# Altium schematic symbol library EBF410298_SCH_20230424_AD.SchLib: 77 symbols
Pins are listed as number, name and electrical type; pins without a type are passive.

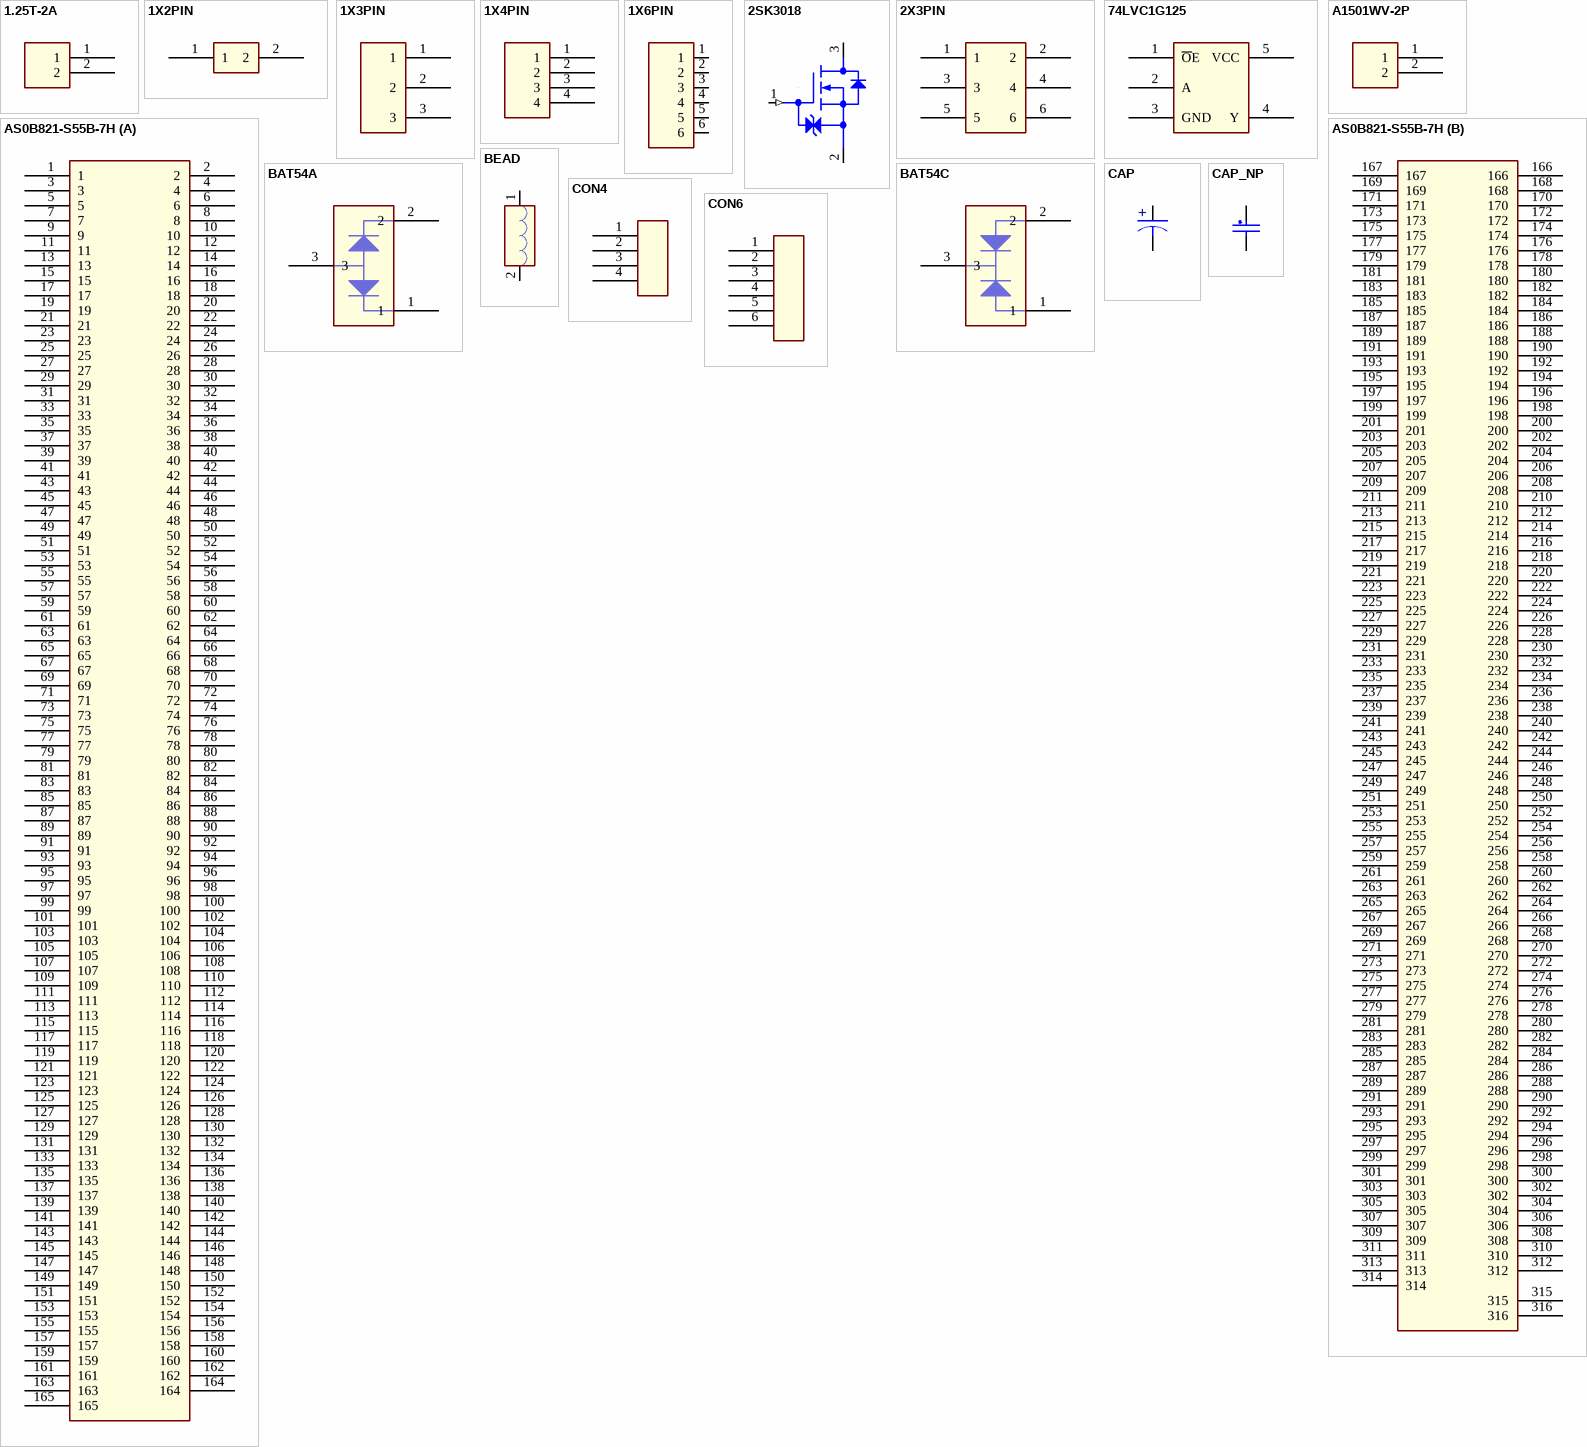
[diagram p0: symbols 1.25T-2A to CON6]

## 1.25T-2A
designator J?
footprint gh1p25_th_2p
pins: 1, 2

## 1X2PIN
designator J?
pins: 1, 2

## 1X3PIN
designator J?
pins: 1, 2, 3

## 1X4PIN
designator J?
pins: 1, 2, 3, 4

## 1X6PIN
designator J?
pins: 1, 2, 3, 4, 5, 6

## 2SK3018
designator Q?
CLASS: IC
pins: 1 GATE (in), 2 SOURCE, 3 DRAIN

## 2X3PIN
designator J?
pins: 1, 2, 3, 4, 5, 6

## 74LVC1G125
designator U?
footprint SOT-353
pins: 1 ~{O}E, 2 A, 3 GND, 4 Y, 5 VCC

## A1501WV-2P
designator J?
pins: 1, 2

## AS0B821-S55B-7H
designator J?
footprint AS0B821-S55B-7H
part A pins: 1, 2, 3, 4, 5, 6, 7, 8, 9, 10, 11, 12, 13, 14, 15, 16, 17, 18, 19, 20, 21, 22, 23, 24, 25, 26, 27, 28, 29, 30, 31, 32, 33, 34, 35, 36, 37, 38, 39, 40, 41, 42, 43, 44, 45, 46, 47, 48, 49, 50, 51, 52, 53, 54, 55, 56, 57, 58, 59, 60, 61, 62, 63, 64, 65, 66, 67, 68, 69, 70, 71, 72, 73, 74, 75, 76, 77, 78, 79, 80, 81, 82, 83, 84, 85, 86, 87, 88, 89, 90, 91, 92, 93, 94, 95, 96, 97, 98, 99, 100, 101, 102, 103, 104, 105, 106, 107, 108, 109, 110, 111, 112, 113, 114, 115, 116, 117, 118, 119, 120, 121, 122, 123, 124, 125, 126, 127, 128, 129, 130, 131, 132, 133, 134, 135, 136, 137, 138, 139, 140, 141, 142, 143, 144, 145, 146, 147, 148, 149, 150, 151, 152, 153, 154, 155, 156, 157, 158, 159, 160, 161, 162, 163, 164, 165
part B pins: 166, 167, 168, 169, 170, 171, 172, 173, 174, 175, 176, 177, 178, 179, 180, 181, 182, 183, 184, 185, 186, 187, 188, 189, 190, 191, 192, 193, 194, 195, 196, 197, 198, 199, 200, 201, 202, 203, 204, 205, 206, 207, 208, 209, 210, 211, 212, 213, 214, 215, 216, 217, 218, 219, 220, 221, 222, 223, 224, 225, 226, 227, 228, 229, 230, 231, 232, 233, 234, 235, 236, 237, 238, 239, 240, 241, 242, 243, 244, 245, 246, 247, 248, 249, 250, 251, 252, 253, 254, 255, 256, 257, 258, 259, 260, 261, 262, 263, 264, 265, 266, 267, 268, 269, 270, 271, 272, 273, 274, 275, 276, 277, 278, 279, 280, 281, 282, 283, 284, 285, 286, 287, 288, 289, 290, 291, 292, 293, 294, 295, 296, 297, 298, 299, 300, 301, 302, 303, 304, 305, 306, 307, 308, 309, 310, 311, 312, 313, 314, 315, 316

## BAT54A
designator D?
footprint SOT23
pins: 1, 2, 3

## BAT54C
designator D?
footprint SOT23
pins: 1, 2, 3

## BEAD
designator L?
CLASS: DISCRETE
pins: 1, 2

## CAP
designator C?
footprint T2012
pins: 1, 2

## CAP_NP
designator C?
CLASS: DISCRETE
pins: 1, 2

## CON4
designator J?
pins: 1, 2, 3, 4

## CON6
designator J?
pins: 1, 2, 3, 4, 5, 6

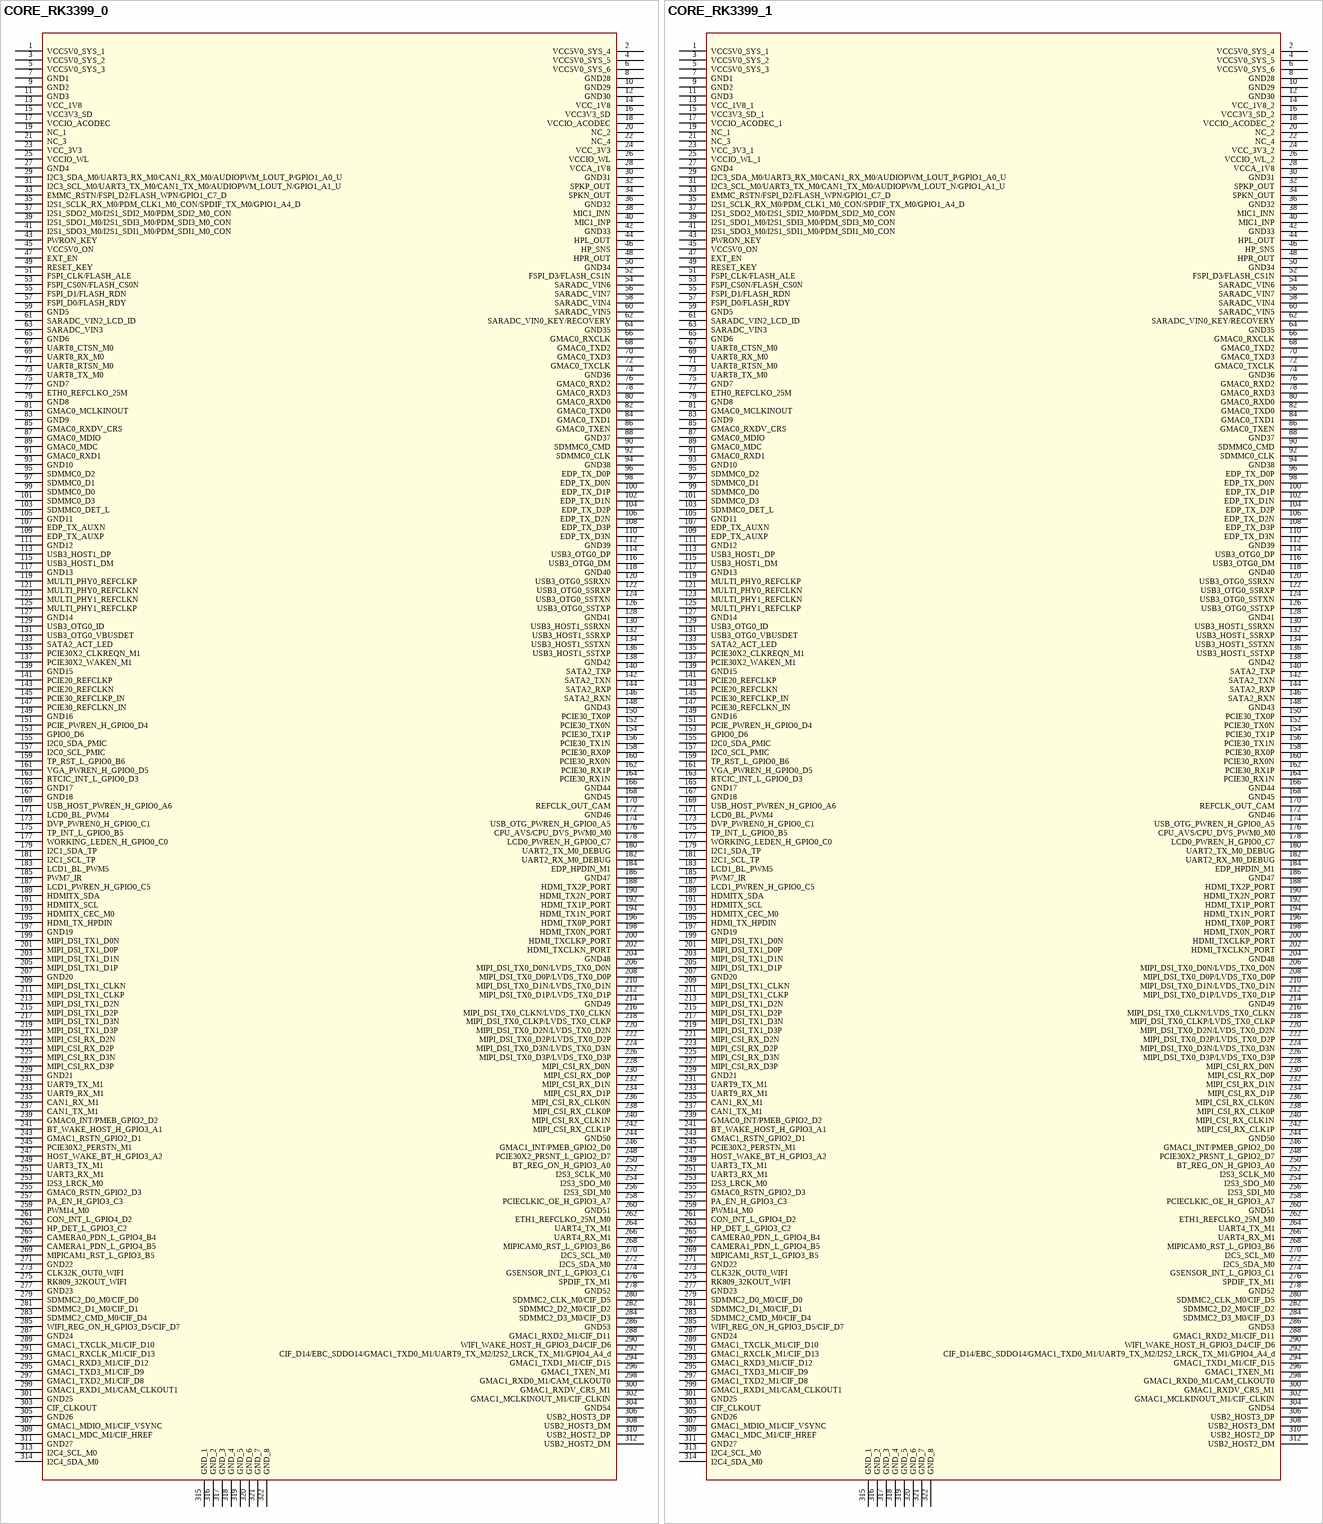
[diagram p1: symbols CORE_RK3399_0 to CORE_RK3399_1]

## CORE_RK3399_0
designator U?
pins: 1 VCC5V0_SYS_1, 2 VCC5V0_SYS_4, 3 VCC5V0_SYS_2, 4 VCC5V0_SYS_5, 5 VCC5V0_SYS_3, 6 VCC5V0_SYS_6, 7 GND1, 8 GND28, 9 GND2, 10 GND29, 11 GND3, 12 GND30, 13 VCC_1V8, 14 VCC_1V8, 15 VCC3V3_SD, 16 VCC3V3_SD, 17 VCCIO_ACODEC, 18 VCCIO_ACODEC, 19 NC_1, 20 NC_2, 21 NC_3, 22 NC_4, 23 VCC_3V3, 24 VCC_3V3, 25 VCCIO_WL, 26 VCCIO_WL, 27 GND4, 28 VCCA_1V8, 29 I2C3_SDA_M0/UART3_RX_M0/CAN1_RX_M0/AUDIOPWM_LOUT_P/GPIO1_A0_U, 30 GND31, 31 I2C3_SCL_M0/UART3_TX_M0/CAN1_TX_M0/AUDIOPWM_LOUT_N/GPIO1_A1_U, 32 SPKP_OUT, 33 EMMC_RSTN/FSPI_D2/FLASH_WPN/GPIO1_C7_D, 34 SPKN_OUT, 35 I2S1_SCLK_RX_M0/PDM_CLK1_M0_CON/SPDIF_TX_M0/GPIO1_A4_D, 36 GND32, 37 I2S1_SDO2_M0/I2S1_SDI2_M0/PDM_SDI2_M0_CON, 38 MIC1_INN, 39 I2S1_SDO1_M0/I2S1_SDI3_M0/PDM_SDI3_M0_CON, 40 MIC1_INP, 41 I2S1_SDO3_M0/I2S1_SDI1_M0/PDM_SDI1_M0_CON, 42 GND33, 43 PWRON_KEY, 44 HPL_OUT, 45 VCC5V0_ON, 46 HP_SNS, 47 EXT_EN, 48 HPR_OUT, 49 RESET_KEY, 50 GND34, 51 FSPI_CLK/FLASH_ALE, 52 FSPI_D3/FLASH_CS1N, 53 FSPI_CS0N/FLASH_CS0N, 54 SARADC_VIN6, 55 FSPI_D1/FLASH_RDN, 56 SARADC_VIN7, 57 FSPI_D0/FLASH_RDY, 58 SARADC_VIN4, 59 GND5, 60 SARADC_VIN5, 61 SARADC_VIN2_LCD_ID, 62 SARADC_VIN0_KEY/RECOVERY, 63 SARADC_VIN3, 64 GND35, 65 GND6, 66 GMAC0_RXCLK, 67 UART8_CTSN_M0, 68 GMAC0_TXD2, 69 UART8_RX_M0, 70 GMAC0_TXD3, 71 UART8_RTSN_M0, 72 GMAC0_TXCLK, 73 UART8_TX_M0, 74 GND36, 75 GND7, 76 GMAC0_RXD2, 77 ETH0_REFCLKO_25M, 78 GMAC0_RXD3, 79 GND8, 80 GMAC0_RXD0, 81 GMAC0_MCLKINOUT, 82 GMAC0_TXD0, 83 GND9, 84 GMAC0_TXD1, 85 GMAC0_RXDV_CRS, 86 GMAC0_TXEN, 87 GMAC0_MDIO, 88 GND37, 89 GMAC0_MDC, 90 SDMMC0_CMD, 91 GMAC0_RXD1, 92 SDMMC0_CLK, 93 GND10, 94 GND38, 95 SDMMC0_D2, 96 EDP_TX_D0P, 97 SDMMC0_D1, 98 EDP_TX_D0N, 99 SDMMC0_D0, 100 EDP_TX_D1P, 101 SDMMC0_D3, 102 EDP_TX_D1N, 103 SDMMC0_DET_L, 104 EDP_TX_D2P, 105 GND11, 106 EDP_TX_D2N, 107 EDP_TX_AUXN, 108 EDP_TX_D3P, 109 EDP_TX_AUXP, 110 EDP_TX_D3N, 111 GND12, 112 GND39, 113 USB3_HOST1_DP, 114 USB3_OTG0_DP, 115 USB3_HOST1_DM, 116 USB3_OTG0_DM, 117 GND13, 118 GND40, 119 MULTI_PHY0_REFCLKP, 120 USB3_OTG0_SSRXN, 121 MULTI_PHY0_REFCLKN, 122 USB3_OTG0_SSRXP, 123 MULTI_PHY1_REFCLKN, 124 USB3_OTG0_SSTXN, 125 MULTI_PHY1_REFCLKP, 126 USB3_OTG0_SSTXP, 127 GND14, 128 GND41, 129 USB3_OTG0_ID, 130 USB3_HOST1_SSRXN, 131 USB3_OTG0_VBUSDET, 132 USB3_HOST1_SSRXP, 133 SATA2_ACT_LED, 134 USB3_HOST1_SSTXN, 135 PCIE30X2_CLKREQN_M1, 136 USB3_HOST1_SSTXP, 137 PCIE30X2_WAKEN_M1, 138 GND42, 139 GND15, 140 SATA2_TXP, 141 PCIE20_REFCLKP, 142 SATA2_TXN, 143 PCIE20_REFCLKN, 144 SATA2_RXP, 145 PCIE30_REFCLKP_IN, 146 SATA2_RXN, 147 PCIE30_REFCLKN_IN, 148 GND43, 149 GND16, 150 PCIE30_TX0P, 151 PCIE_PWREN_H_GPIO0_D4, 152 PCIE30_TX0N, 153 GPIO0_D6, 154 PCIE30_TX1P, 155 I2C0_SDA_PMIC, 156 PCIE30_TX1N, 157 I2C0_SCL_PMIC, 158 PCIE30_RX0P, 159 TP_RST_L_GPIO0_B6, 160 PCIE30_RX0N, 161 VGA_PWREN_H_GPIO0_D5, 162 PCIE30_RX1P, 163 RTCIC_INT_L_GPIO0_D3, 164 PCIE30_RX1N, 165 GND17, 166 GND44, 167 GND18, 168 GND45, 169 USB_HOST_PWREN_H_GPIO0_A6, 170 REFCLK_OUT_CAM, 171 LCD0_BL_PWM4, 172 GND46, 173 DVP_PWREN0_H_GPIO0_C1, 174 USB_OTG_PWREN_H_GPIO0_A5, 175 TP_INT_L_GPIO0_B5, 176 CPU_AVS/CPU_DVS_PWM0_M0, 177 WORKING_LEDEN_H_GPIO0_C0, 178 LCD0_PWREN_H_GPIO0_C7, 179 I2C1_SDA_TP, 180 UART2_TX_M0_DEBUG, 181 I2C1_SCL_TP, 182 UART2_RX_M0_DEBUG, 183 LCD1_BL_PWM5, 184 EDP_HPDIN_M1, 185 PWM7_IR, 186 GND47, 187 LCD1_PWREN_H_GPIO0_C5, 188 HDMI_TX2P_PORT, 189 HDMITX_SDA, 190 HDMI_TX2N_PORT, 191 HDMITX_SCL, 192 HDMI_TX1P_PORT, 193 HDMITX_CEC_M0, 194 HDMI_TX1N_PORT, 195 HDMI_TX_HPDIN, 196 HDMI_TX0P_PORT, 197 GND19, 198 HDMI_TX0N_PORT, 199 MIPI_DSI_TX1_D0N, 200 HDMI_TXCLKP_PORT, 201 MIPI_DSI_TX1_D0P, 202 HDMI_TXCLKN_PORT, 203 MIPI_DSI_TX1_D1N, 204 GND48, 205 MIPI_DSI_TX1_D1P, 206 MIPI_DSI_TX0_D0N/LVDS_TX0_D0N, 207 GND20, 208 MIPI_DSI_TX0_D0P/LVDS_TX0_D0P, 209 MIPI_DSI_TX1_CLKN, 210 MIPI_DSI_TX0_D1N/LVDS_TX0_D1N, 211 MIPI_DSI_TX1_CLKP, 212 MIPI_DSI_TX0_D1P/LVDS_TX0_D1P, 213 MIPI_DSI_TX1_D2N, 214 GND49, 215 MIPI_DSI_TX1_D2P, 216 MIPI_DSI_TX0_CLKN/LVDS_TX0_CLKN, 217 MIPI_DSI_TX1_D3N, 218 MIPI_DSI_TX0_CLKP/LVDS_TX0_CLKP, 219 MIPI_DSI_TX1_D3P, 220 MIPI_DSI_TX0_D2N/LVDS_TX0_D2N, 221 MIPI_CSI_RX_D2N, 222 MIPI_DSI_TX0_D2P/LVDS_TX0_D2P, 223 MIPI_CSI_RX_D2P, 224 MIPI_DSI_TX0_D3N/LVDS_TX0_D3N, 225 MIPI_CSI_RX_D3N, 226 MIPI_DSI_TX0_D3P/LVDS_TX0_D3P, 227 MIPI_CSI_RX_D3P, 228 MIPI_CSI_RX_D0N, 229 GND21, 230 MIPI_CSI_RX_D0P, 231 UART9_TX_M1, 232 MIPI_CSI_RX_D1N, 233 UART9_RX_M1, 234 MIPI_CSI_RX_D1P, 235 CAN1_RX_M1, 236 MIPI_CSI_RX_CLK0N, 237 CAN1_TX_M1, 238 MIPI_CSI_RX_CLK0P, 239 GMAC0_INT/PMEB_GPIO2_D2, 240 MIPI_CSI_RX_CLK1N, 241 BT_WAKE_HOST_H_GPIO3_A1, 242 MIPI_CSI_RX_CLK1P, 243 GMAC1_RSTN_GPIO2_D1, 244 GND50, 245 PCIE30X2_PERSTN_M1, 246 GMAC1_INT/PMEB_GPIO2_D0, 247 HOST_WAKE_BT_H_GPIO3_A2, 248 PCIE30X2_PRSNT_L_GPIO2_D7, 249 UART3_TX_M1, 250 BT_REG_ON_H_GPIO3_A0, 251 UART3_RX_M1, 252 I2S3_SCLK_M0, 253 I2S3_LRCK_M0, 254 I2S3_SDO_M0, 255 GMAC0_RSTN_GPIO2_D3, 256 I2S3_SDI_M0, 257 PA_EN_H_GPIO3_C3, 258 PCIECLKIC_OE_H_GPIO3_A7, 259 PWM14_M0, 260 GND51, 261 CON_INT_L_GPIO4_D2, 262 ETH1_REFCLKO_25M_M0, 263 HP_DET_L_GPIO3_C2, 264 UART4_TX_M1, 265 CAMERA0_PDN_L_GPIO4_B4, 266 UART4_RX_M1, 267 CAMERA1_PDN_L_GPIO4_B5, 268 MIPICAM0_RST_L_GPIO3_B6, 269 MIPICAM1_RST_L_GPIO3_B5, 270 I2C5_SCL_M0, 271 GND22, 272 I2C5_SDA_M0, 273 CLK32K_OUT0_WIFI, 274 GSENSOR_INT_L_GPIO3_C1, 275 RK809_32KOUT_WIFI, 276 SPDIF_TX_M1, 277 GND23, 278 GND52, 279 SDMMC2_D0_M0/CIF_D0, 280 SDMMC2_CLK_M0/CIF_D5, 281 SDMMC2_D1_M0/CIF_D1, 282 SDMMC2_D2_M0/CIF_D2, 283 SDMMC2_CMD_M0/CIF_D4, 284 SDMMC2_D3_M0/CIF_D3, 285 WIFI_REG_ON_H_GPIO3_D5/CIF_D7, 286 GND53, 287 GND24, 288 GMAC1_RXD2_M1/CIF_D11, 289 GMAC1_TXCLK_M1/CIF_D10, 290 WIFI_WAKE_HOST_H_GPIO3_D4/CIF_D6, 291 GMAC1_RXCLK_M1/CIF_D13, 292 CIF_D14/EBC_SDDO14/GMAC1_TXD0_M1/UART9_TX_M2/I2S2_LRCK_TX_M1/GPIO4_A4_d, 293 GMAC1_RXD3_M1/CIF_D12, 294 GMAC1_TXD1_M1/CIF_D15, 295 GMAC1_TXD3_M1/CIF_D9, 296 GMAC1_TXEN_M1, 297 GMAC1_TXD2_M1/CIF_D8, 298 GMAC1_RXD0_M1/CAM_CLKOUT0, 299 GMAC1_RXD1_M1/CAM_CLKOUT1, 300 GMAC1_RXDV_CRS_M1, 301 GND25, 302 GMAC1_MCLKINOUT_M1/CIF_CLKIN, 303 CIF_CLKOUT, 304 GND54, 305 GND26, 306 USB2_HOST3_DP, 307 GMAC1_MDIO_M1/CIF_VSYNC, 308 USB2_HOST3_DM, 309 GMAC1_MDC_M1/CIF_HREF, 310 USB2_HOST2_DP, 311 GND27, 312 USB2_HOST2_DM, 313 I2C4_SCL_M0, 314 I2C4_SDA_M0, 315 GND_1, 316 GND_2, 317 GND_3, 318 GND_4, 319 GND_5, 320 GND_6, 321 GND_7, 322 GND_8

## CORE_RK3399_1
designator U?
pins: 1 VCC5V0_SYS_1, 2 VCC5V0_SYS_4, 3 VCC5V0_SYS_2, 4 VCC5V0_SYS_5, 5 VCC5V0_SYS_3, 6 VCC5V0_SYS_6, 7 GND1, 8 GND28, 9 GND2, 10 GND29, 11 GND3, 12 GND30, 13 VCC_1V8_1, 14 VCC_1V8_2, 15 VCC3V3_SD_1, 16 VCC3V3_SD_2, 17 VCCIO_ACODEC_1, 18 VCCIO_ACODEC_2, 19 NC_1, 20 NC_2, 21 NC_3, 22 NC_4, 23 VCC_3V3_1, 24 VCC_3V3_2, 25 VCCIO_WL_1, 26 VCCIO_WL_2, 27 GND4, 28 VCCA_1V8, 29 I2C3_SDA_M0/UART3_RX_M0/CAN1_RX_M0/AUDIOPWM_LOUT_P/GPIO1_A0_U, 30 GND31, 31 I2C3_SCL_M0/UART3_TX_M0/CAN1_TX_M0/AUDIOPWM_LOUT_N/GPIO1_A1_U, 32 SPKP_OUT, 33 EMMC_RSTN/FSPI_D2/FLASH_WPN/GPIO1_C7_D, 34 SPKN_OUT, 35 I2S1_SCLK_RX_M0/PDM_CLK1_M0_CON/SPDIF_TX_M0/GPIO1_A4_D, 36 GND32, 37 I2S1_SDO2_M0/I2S1_SDI2_M0/PDM_SDI2_M0_CON, 38 MIC1_INN, 39 I2S1_SDO1_M0/I2S1_SDI3_M0/PDM_SDI3_M0_CON, 40 MIC1_INP, 41 I2S1_SDO3_M0/I2S1_SDI1_M0/PDM_SDI1_M0_CON, 42 GND33, 43 PWRON_KEY, 44 HPL_OUT, 45 VCC5V0_ON, 46 HP_SNS, 47 EXT_EN, 48 HPR_OUT, 49 RESET_KEY, 50 GND34, 51 FSPI_CLK/FLASH_ALE, 52 FSPI_D3/FLASH_CS1N, 53 FSPI_CS0N/FLASH_CS0N, 54 SARADC_VIN6, 55 FSPI_D1/FLASH_RDN, 56 SARADC_VIN7, 57 FSPI_D0/FLASH_RDY, 58 SARADC_VIN4, 59 GND5, 60 SARADC_VIN5, 61 SARADC_VIN2_LCD_ID, 62 SARADC_VIN0_KEY/RECOVERY, 63 SARADC_VIN3, 64 GND35, 65 GND6, 66 GMAC0_RXCLK, 67 UART8_CTSN_M0, 68 GMAC0_TXD2, 69 UART8_RX_M0, 70 GMAC0_TXD3, 71 UART8_RTSN_M0, 72 GMAC0_TXCLK, 73 UART8_TX_M0, 74 GND36, 75 GND7, 76 GMAC0_RXD2, 77 ETH0_REFCLKO_25M, 78 GMAC0_RXD3, 79 GND8, 80 GMAC0_RXD0, 81 GMAC0_MCLKINOUT, 82 GMAC0_TXD0, 83 GND9, 84 GMAC0_TXD1, 85 GMAC0_RXDV_CRS, 86 GMAC0_TXEN, 87 GMAC0_MDIO, 88 GND37, 89 GMAC0_MDC, 90 SDMMC0_CMD, 91 GMAC0_RXD1, 92 SDMMC0_CLK, 93 GND10, 94 GND38, 95 SDMMC0_D2, 96 EDP_TX_D0P, 97 SDMMC0_D1, 98 EDP_TX_D0N, 99 SDMMC0_D0, 100 EDP_TX_D1P, 101 SDMMC0_D3, 102 EDP_TX_D1N, 103 SDMMC0_DET_L, 104 EDP_TX_D2P, 105 GND11, 106 EDP_TX_D2N, 107 EDP_TX_AUXN, 108 EDP_TX_D3P, 109 EDP_TX_AUXP, 110 EDP_TX_D3N, 111 GND12, 112 GND39, 113 USB3_HOST1_DP, 114 USB3_OTG0_DP, 115 USB3_HOST1_DM, 116 USB3_OTG0_DM, 117 GND13, 118 GND40, 119 MULTI_PHY0_REFCLKP, 120 USB3_OTG0_SSRXN, 121 MULTI_PHY0_REFCLKN, 122 USB3_OTG0_SSRXP, 123 MULTI_PHY1_REFCLKN, 124 USB3_OTG0_SSTXN, 125 MULTI_PHY1_REFCLKP, 126 USB3_OTG0_SSTXP, 127 GND14, 128 GND41, 129 USB3_OTG0_ID, 130 USB3_HOST1_SSRXN, 131 USB3_OTG0_VBUSDET, 132 USB3_HOST1_SSRXP, 133 SATA2_ACT_LED, 134 USB3_HOST1_SSTXN, 135 PCIE30X2_CLKREQN_M1, 136 USB3_HOST1_SSTXP, 137 PCIE30X2_WAKEN_M1, 138 GND42, 139 GND15, 140 SATA2_TXP, 141 PCIE20_REFCLKP, 142 SATA2_TXN, 143 PCIE20_REFCLKN, 144 SATA2_RXP, 145 PCIE30_REFCLKP_IN, 146 SATA2_RXN, 147 PCIE30_REFCLKN_IN, 148 GND43, 149 GND16, 150 PCIE30_TX0P, 151 PCIE_PWREN_H_GPIO0_D4, 152 PCIE30_TX0N, 153 GPIO0_D6, 154 PCIE30_TX1P, 155 I2C0_SDA_PMIC, 156 PCIE30_TX1N, 157 I2C0_SCL_PMIC, 158 PCIE30_RX0P, 159 TP_RST_L_GPIO0_B6, 160 PCIE30_RX0N, 161 VGA_PWREN_H_GPIO0_D5, 162 PCIE30_RX1P, 163 RTCIC_INT_L_GPIO0_D3, 164 PCIE30_RX1N, 165 GND17, 166 GND44, 167 GND18, 168 GND45, 169 USB_HOST_PWREN_H_GPIO0_A6, 170 REFCLK_OUT_CAM, 171 LCD0_BL_PWM4, 172 GND46, 173 DVP_PWREN0_H_GPIO0_C1, 174 USB_OTG_PWREN_H_GPIO0_A5, 175 TP_INT_L_GPIO0_B5, 176 CPU_AVS/CPU_DVS_PWM0_M0, 177 WORKING_LEDEN_H_GPIO0_C0, 178 LCD0_PWREN_H_GPIO0_C7, 179 I2C1_SDA_TP, 180 UART2_TX_M0_DEBUG, 181 I2C1_SCL_TP, 182 UART2_RX_M0_DEBUG, 183 LCD1_BL_PWM5, 184 EDP_HPDIN_M1, 185 PWM7_IR, 186 GND47, 187 LCD1_PWREN_H_GPIO0_C5, 188 HDMI_TX2P_PORT, 189 HDMITX_SDA, 190 HDMI_TX2N_PORT, 191 HDMITX_SCL, 192 HDMI_TX1P_PORT, 193 HDMITX_CEC_M0, 194 HDMI_TX1N_PORT, 195 HDMI_TX_HPDIN, 196 HDMI_TX0P_PORT, 197 GND19, 198 HDMI_TX0N_PORT, 199 MIPI_DSI_TX1_D0N, 200 HDMI_TXCLKP_PORT, 201 MIPI_DSI_TX1_D0P, 202 HDMI_TXCLKN_PORT, 203 MIPI_DSI_TX1_D1N, 204 GND48, 205 MIPI_DSI_TX1_D1P, 206 MIPI_DSI_TX0_D0N/LVDS_TX0_D0N, 207 GND20, 208 MIPI_DSI_TX0_D0P/LVDS_TX0_D0P, 209 MIPI_DSI_TX1_CLKN, 210 MIPI_DSI_TX0_D1N/LVDS_TX0_D1N, 211 MIPI_DSI_TX1_CLKP, 212 MIPI_DSI_TX0_D1P/LVDS_TX0_D1P, 213 MIPI_DSI_TX1_D2N, 214 GND49, 215 MIPI_DSI_TX1_D2P, 216 MIPI_DSI_TX0_CLKN/LVDS_TX0_CLKN, 217 MIPI_DSI_TX1_D3N, 218 MIPI_DSI_TX0_CLKP/LVDS_TX0_CLKP, 219 MIPI_DSI_TX1_D3P, 220 MIPI_DSI_TX0_D2N/LVDS_TX0_D2N, 221 MIPI_CSI_RX_D2N, 222 MIPI_DSI_TX0_D2P/LVDS_TX0_D2P, 223 MIPI_CSI_RX_D2P, 224 MIPI_DSI_TX0_D3N/LVDS_TX0_D3N, 225 MIPI_CSI_RX_D3N, 226 MIPI_DSI_TX0_D3P/LVDS_TX0_D3P, 227 MIPI_CSI_RX_D3P, 228 MIPI_CSI_RX_D0N, 229 GND21, 230 MIPI_CSI_RX_D0P, 231 UART9_TX_M1, 232 MIPI_CSI_RX_D1N, 233 UART9_RX_M1, 234 MIPI_CSI_RX_D1P, 235 CAN1_RX_M1, 236 MIPI_CSI_RX_CLK0N, 237 CAN1_TX_M1, 238 MIPI_CSI_RX_CLK0P, 239 GMAC0_INT/PMEB_GPIO2_D2, 240 MIPI_CSI_RX_CLK1N, 241 BT_WAKE_HOST_H_GPIO3_A1, 242 MIPI_CSI_RX_CLK1P, 243 GMAC1_RSTN_GPIO2_D1, 244 GND50, 245 PCIE30X2_PERSTN_M1, 246 GMAC1_INT/PMEB_GPIO2_D0, 247 HOST_WAKE_BT_H_GPIO3_A2, 248 PCIE30X2_PRSNT_L_GPIO2_D7, 249 UART3_TX_M1, 250 BT_REG_ON_H_GPIO3_A0, 251 UART3_RX_M1, 252 I2S3_SCLK_M0, 253 I2S3_LRCK_M0, 254 I2S3_SDO_M0, 255 GMAC0_RSTN_GPIO2_D3, 256 I2S3_SDI_M0, 257 PA_EN_H_GPIO3_C3, 258 PCIECLKIC_OE_H_GPIO3_A7, 259 PWM14_M0, 260 GND51, 261 CON_INT_L_GPIO4_D2, 262 ETH1_REFCLKO_25M_M0, 263 HP_DET_L_GPIO3_C2, 264 UART4_TX_M1, 265 CAMERA0_PDN_L_GPIO4_B4, 266 UART4_RX_M1, 267 CAMERA1_PDN_L_GPIO4_B5, 268 MIPICAM0_RST_L_GPIO3_B6, 269 MIPICAM1_RST_L_GPIO3_B5, 270 I2C5_SCL_M0, 271 GND22, 272 I2C5_SDA_M0, 273 CLK32K_OUT0_WIFI, 274 GSENSOR_INT_L_GPIO3_C1, 275 RK809_32KOUT_WIFI, 276 SPDIF_TX_M1, 277 GND23, 278 GND52, 279 SDMMC2_D0_M0/CIF_D0, 280 SDMMC2_CLK_M0/CIF_D5, 281 SDMMC2_D1_M0/CIF_D1, 282 SDMMC2_D2_M0/CIF_D2, 283 SDMMC2_CMD_M0/CIF_D4, 284 SDMMC2_D3_M0/CIF_D3, 285 WIFI_REG_ON_H_GPIO3_D5/CIF_D7, 286 GND53, 287 GND24, 288 GMAC1_RXD2_M1/CIF_D11, 289 GMAC1_TXCLK_M1/CIF_D10, 290 WIFI_WAKE_HOST_H_GPIO3_D4/CIF_D6, 291 GMAC1_RXCLK_M1/CIF_D13, 292 CIF_D14/EBC_SDDO14/GMAC1_TXD0_M1/UART9_TX_M2/I2S2_LRCK_TX_M1/GPIO4_A4_d, 293 GMAC1_RXD3_M1/CIF_D12, 294 GMAC1_TXD1_M1/CIF_D15, 295 GMAC1_TXD3_M1/CIF_D9, 296 GMAC1_TXEN_M1, 297 GMAC1_TXD2_M1/CIF_D8, 298 GMAC1_RXD0_M1/CAM_CLKOUT0, 299 GMAC1_RXD1_M1/CAM_CLKOUT1, 300 GMAC1_RXDV_CRS_M1, 301 GND25, 302 GMAC1_MCLKINOUT_M1/CIF_CLKIN, 303 CIF_CLKOUT, 304 GND54, 305 GND26, 306 USB2_HOST3_DP, 307 GMAC1_MDIO_M1/CIF_VSYNC, 308 USB2_HOST3_DM, 309 GMAC1_MDC_M1/CIF_HREF, 310 USB2_HOST2_DP, 311 GND27, 312 USB2_HOST2_DM, 313 I2C4_SCL_M0, 314 I2C4_SDA_M0, 315 GND_1, 316 GND_2, 317 GND_3, 318 GND_4, 319 GND_5, 320 GND_6, 321 GND_7, 322 GND_8

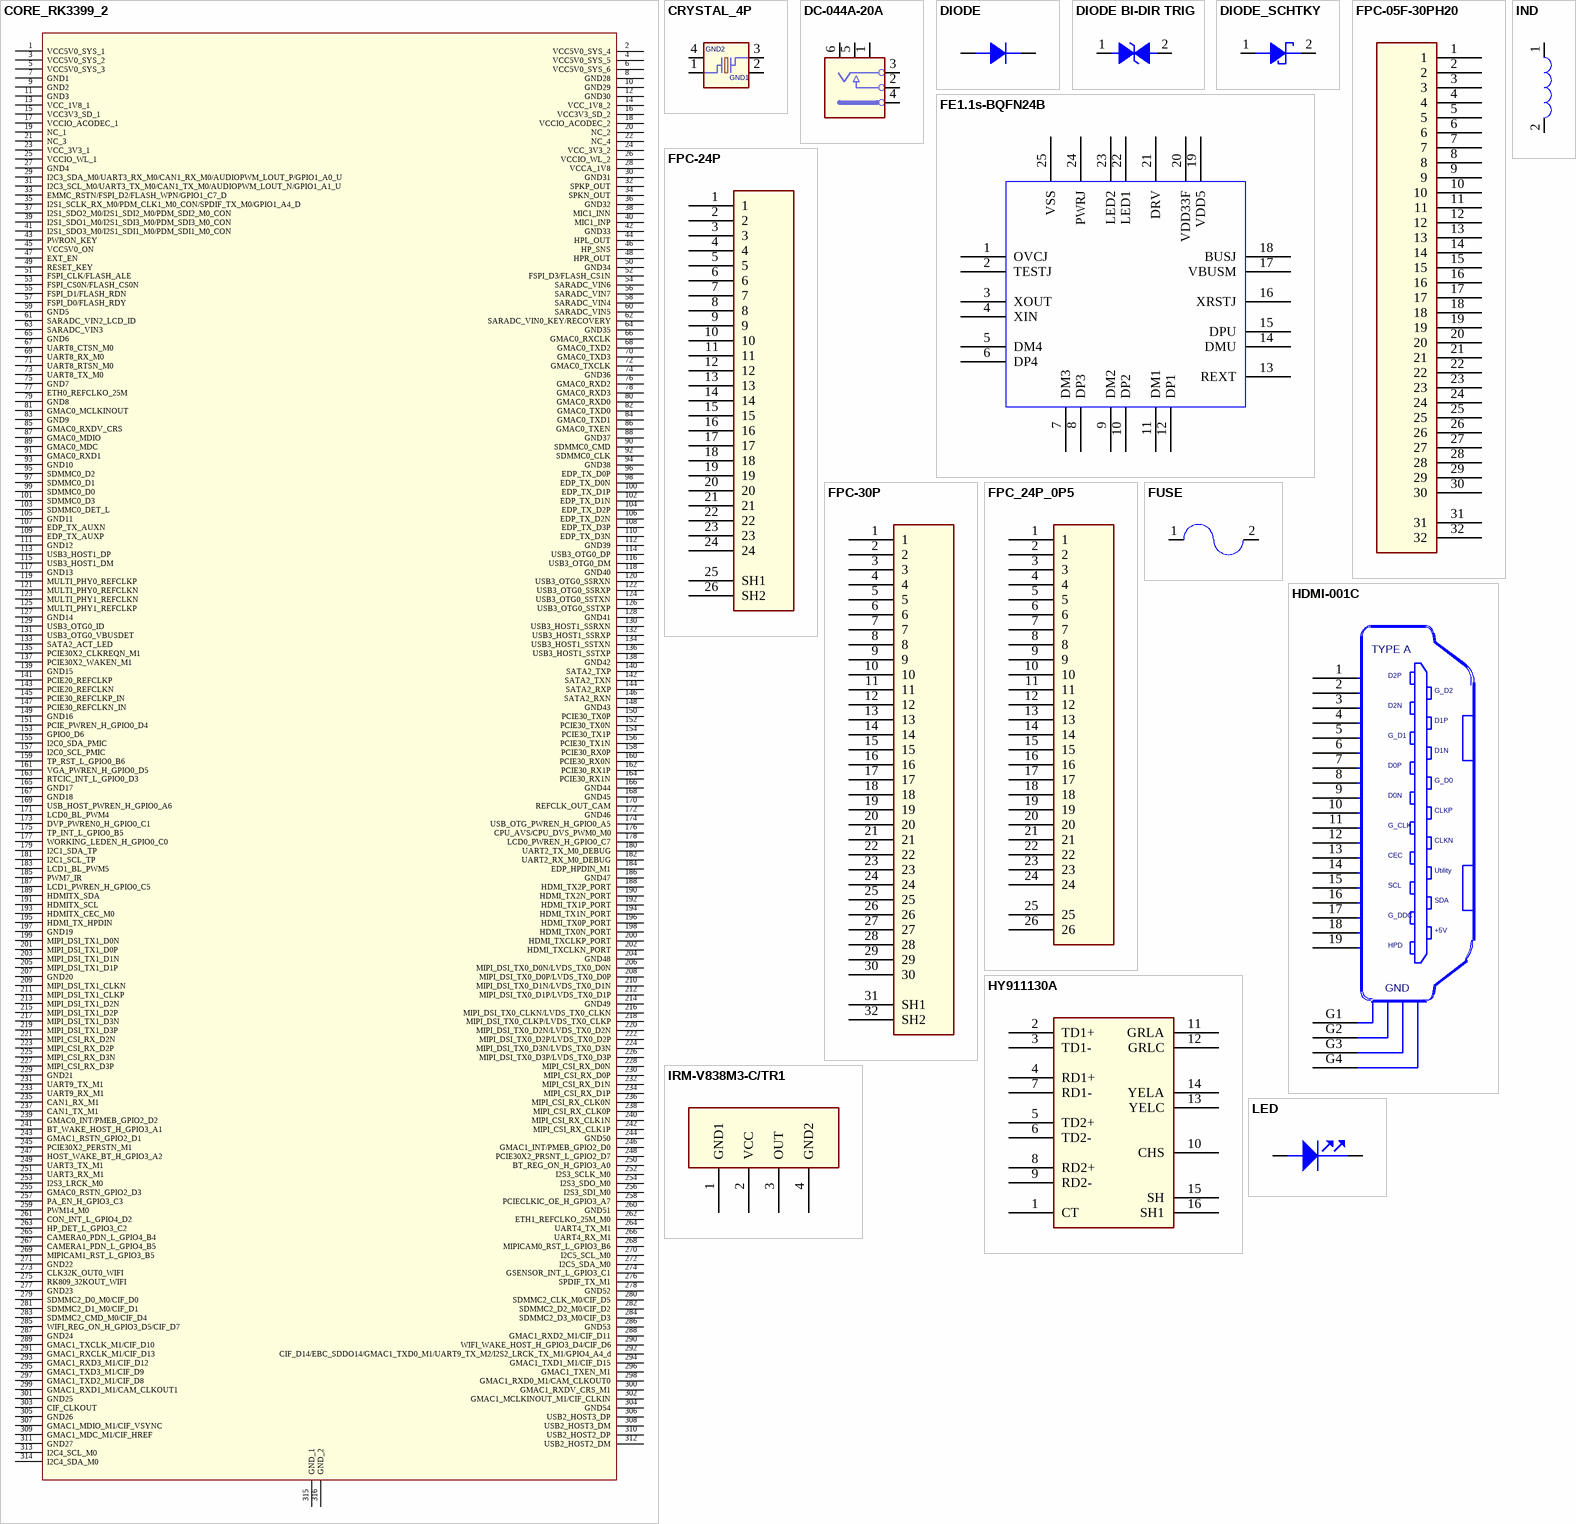
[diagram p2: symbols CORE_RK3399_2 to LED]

## CORE_RK3399_2
designator U?
pins: 1 VCC5V0_SYS_1, 2 VCC5V0_SYS_4, 3 VCC5V0_SYS_2, 4 VCC5V0_SYS_5, 5 VCC5V0_SYS_3, 6 VCC5V0_SYS_6, 7 GND1, 8 GND28, 9 GND2, 10 GND29, 11 GND3, 12 GND30, 13 VCC_1V8_1, 14 VCC_1V8_2, 15 VCC3V3_SD_1, 16 VCC3V3_SD_2, 17 VCCIO_ACODEC_1, 18 VCCIO_ACODEC_2, 19 NC_1, 20 NC_2, 21 NC_3, 22 NC_4, 23 VCC_3V3_1, 24 VCC_3V3_2, 25 VCCIO_WL_1, 26 VCCIO_WL_2, 27 GND4, 28 VCCA_1V8, 29 I2C3_SDA_M0/UART3_RX_M0/CAN1_RX_M0/AUDIOPWM_LOUT_P/GPIO1_A0_U, 30 GND31, 31 I2C3_SCL_M0/UART3_TX_M0/CAN1_TX_M0/AUDIOPWM_LOUT_N/GPIO1_A1_U, 32 SPKP_OUT, 33 EMMC_RSTN/FSPI_D2/FLASH_WPN/GPIO1_C7_D, 34 SPKN_OUT, 35 I2S1_SCLK_RX_M0/PDM_CLK1_M0_CON/SPDIF_TX_M0/GPIO1_A4_D, 36 GND32, 37 I2S1_SDO2_M0/I2S1_SDI2_M0/PDM_SDI2_M0_CON, 38 MIC1_INN, 39 I2S1_SDO1_M0/I2S1_SDI3_M0/PDM_SDI3_M0_CON, 40 MIC1_INP, 41 I2S1_SDO3_M0/I2S1_SDI1_M0/PDM_SDI1_M0_CON, 42 GND33, 43 PWRON_KEY, 44 HPL_OUT, 45 VCC5V0_ON, 46 HP_SNS, 47 EXT_EN, 48 HPR_OUT, 49 RESET_KEY, 50 GND34, 51 FSPI_CLK/FLASH_ALE, 52 FSPI_D3/FLASH_CS1N, 53 FSPI_CS0N/FLASH_CS0N, 54 SARADC_VIN6, 55 FSPI_D1/FLASH_RDN, 56 SARADC_VIN7, 57 FSPI_D0/FLASH_RDY, 58 SARADC_VIN4, 59 GND5, 60 SARADC_VIN5, 61 SARADC_VIN2_LCD_ID, 62 SARADC_VIN0_KEY/RECOVERY, 63 SARADC_VIN3, 64 GND35, 65 GND6, 66 GMAC0_RXCLK, 67 UART8_CTSN_M0, 68 GMAC0_TXD2, 69 UART8_RX_M0, 70 GMAC0_TXD3, 71 UART8_RTSN_M0, 72 GMAC0_TXCLK, 73 UART8_TX_M0, 74 GND36, 75 GND7, 76 GMAC0_RXD2, 77 ETH0_REFCLKO_25M, 78 GMAC0_RXD3, 79 GND8, 80 GMAC0_RXD0, 81 GMAC0_MCLKINOUT, 82 GMAC0_TXD0, 83 GND9, 84 GMAC0_TXD1, 85 GMAC0_RXDV_CRS, 86 GMAC0_TXEN, 87 GMAC0_MDIO, 88 GND37, 89 GMAC0_MDC, 90 SDMMC0_CMD, 91 GMAC0_RXD1, 92 SDMMC0_CLK, 93 GND10, 94 GND38, 95 SDMMC0_D2, 96 EDP_TX_D0P, 97 SDMMC0_D1, 98 EDP_TX_D0N, 99 SDMMC0_D0, 100 EDP_TX_D1P, 101 SDMMC0_D3, 102 EDP_TX_D1N, 103 SDMMC0_DET_L, 104 EDP_TX_D2P, 105 GND11, 106 EDP_TX_D2N, 107 EDP_TX_AUXN, 108 EDP_TX_D3P, 109 EDP_TX_AUXP, 110 EDP_TX_D3N, 111 GND12, 112 GND39, 113 USB3_HOST1_DP, 114 USB3_OTG0_DP, 115 USB3_HOST1_DM, 116 USB3_OTG0_DM, 117 GND13, 118 GND40, 119 MULTI_PHY0_REFCLKP, 120 USB3_OTG0_SSRXN, 121 MULTI_PHY0_REFCLKN, 122 USB3_OTG0_SSRXP, 123 MULTI_PHY1_REFCLKN, 124 USB3_OTG0_SSTXN, 125 MULTI_PHY1_REFCLKP, 126 USB3_OTG0_SSTXP, 127 GND14, 128 GND41, 129 USB3_OTG0_ID, 130 USB3_HOST1_SSRXN, 131 USB3_OTG0_VBUSDET, 132 USB3_HOST1_SSRXP, 133 SATA2_ACT_LED, 134 USB3_HOST1_SSTXN, 135 PCIE30X2_CLKREQN_M1, 136 USB3_HOST1_SSTXP, 137 PCIE30X2_WAKEN_M1, 138 GND42, 139 GND15, 140 SATA2_TXP, 141 PCIE20_REFCLKP, 142 SATA2_TXN, 143 PCIE20_REFCLKN, 144 SATA2_RXP, 145 PCIE30_REFCLKP_IN, 146 SATA2_RXN, 147 PCIE30_REFCLKN_IN, 148 GND43, 149 GND16, 150 PCIE30_TX0P, 151 PCIE_PWREN_H_GPIO0_D4, 152 PCIE30_TX0N, 153 GPIO0_D6, 154 PCIE30_TX1P, 155 I2C0_SDA_PMIC, 156 PCIE30_TX1N, 157 I2C0_SCL_PMIC, 158 PCIE30_RX0P, 159 TP_RST_L_GPIO0_B6, 160 PCIE30_RX0N, 161 VGA_PWREN_H_GPIO0_D5, 162 PCIE30_RX1P, 163 RTCIC_INT_L_GPIO0_D3, 164 PCIE30_RX1N, 165 GND17, 166 GND44, 167 GND18, 168 GND45, 169 USB_HOST_PWREN_H_GPIO0_A6, 170 REFCLK_OUT_CAM, 171 LCD0_BL_PWM4, 172 GND46, 173 DVP_PWREN0_H_GPIO0_C1, 174 USB_OTG_PWREN_H_GPIO0_A5, 175 TP_INT_L_GPIO0_B5, 176 CPU_AVS/CPU_DVS_PWM0_M0, 177 WORKING_LEDEN_H_GPIO0_C0, 178 LCD0_PWREN_H_GPIO0_C7, 179 I2C1_SDA_TP, 180 UART2_TX_M0_DEBUG, 181 I2C1_SCL_TP, 182 UART2_RX_M0_DEBUG, 183 LCD1_BL_PWM5, 184 EDP_HPDIN_M1, 185 PWM7_IR, 186 GND47, 187 LCD1_PWREN_H_GPIO0_C5, 188 HDMI_TX2P_PORT, 189 HDMITX_SDA, 190 HDMI_TX2N_PORT, 191 HDMITX_SCL, 192 HDMI_TX1P_PORT, 193 HDMITX_CEC_M0, 194 HDMI_TX1N_PORT, 195 HDMI_TX_HPDIN, 196 HDMI_TX0P_PORT, 197 GND19, 198 HDMI_TX0N_PORT, 199 MIPI_DSI_TX1_D0N, 200 HDMI_TXCLKP_PORT, 201 MIPI_DSI_TX1_D0P, 202 HDMI_TXCLKN_PORT, 203 MIPI_DSI_TX1_D1N, 204 GND48, 205 MIPI_DSI_TX1_D1P, 206 MIPI_DSI_TX0_D0N/LVDS_TX0_D0N, 207 GND20, 208 MIPI_DSI_TX0_D0P/LVDS_TX0_D0P, 209 MIPI_DSI_TX1_CLKN, 210 MIPI_DSI_TX0_D1N/LVDS_TX0_D1N, 211 MIPI_DSI_TX1_CLKP, 212 MIPI_DSI_TX0_D1P/LVDS_TX0_D1P, 213 MIPI_DSI_TX1_D2N, 214 GND49, 215 MIPI_DSI_TX1_D2P, 216 MIPI_DSI_TX0_CLKN/LVDS_TX0_CLKN, 217 MIPI_DSI_TX1_D3N, 218 MIPI_DSI_TX0_CLKP/LVDS_TX0_CLKP, 219 MIPI_DSI_TX1_D3P, 220 MIPI_DSI_TX0_D2N/LVDS_TX0_D2N, 221 MIPI_CSI_RX_D2N, 222 MIPI_DSI_TX0_D2P/LVDS_TX0_D2P, 223 MIPI_CSI_RX_D2P, 224 MIPI_DSI_TX0_D3N/LVDS_TX0_D3N, 225 MIPI_CSI_RX_D3N, 226 MIPI_DSI_TX0_D3P/LVDS_TX0_D3P, 227 MIPI_CSI_RX_D3P, 228 MIPI_CSI_RX_D0N, 229 GND21, 230 MIPI_CSI_RX_D0P, 231 UART9_TX_M1, 232 MIPI_CSI_RX_D1N, 233 UART9_RX_M1, 234 MIPI_CSI_RX_D1P, 235 CAN1_RX_M1, 236 MIPI_CSI_RX_CLK0N, 237 CAN1_TX_M1, 238 MIPI_CSI_RX_CLK0P, 239 GMAC0_INT/PMEB_GPIO2_D2, 240 MIPI_CSI_RX_CLK1N, 241 BT_WAKE_HOST_H_GPIO3_A1, 242 MIPI_CSI_RX_CLK1P, 243 GMAC1_RSTN_GPIO2_D1, 244 GND50, 245 PCIE30X2_PERSTN_M1, 246 GMAC1_INT/PMEB_GPIO2_D0, 247 HOST_WAKE_BT_H_GPIO3_A2, 248 PCIE30X2_PRSNT_L_GPIO2_D7, 249 UART3_TX_M1, 250 BT_REG_ON_H_GPIO3_A0, 251 UART3_RX_M1, 252 I2S3_SCLK_M0, 253 I2S3_LRCK_M0, 254 I2S3_SDO_M0, 255 GMAC0_RSTN_GPIO2_D3, 256 I2S3_SDI_M0, 257 PA_EN_H_GPIO3_C3, 258 PCIECLKIC_OE_H_GPIO3_A7, 259 PWM14_M0, 260 GND51, 261 CON_INT_L_GPIO4_D2, 262 ETH1_REFCLKO_25M_M0, 263 HP_DET_L_GPIO3_C2, 264 UART4_TX_M1, 265 CAMERA0_PDN_L_GPIO4_B4, 266 UART4_RX_M1, 267 CAMERA1_PDN_L_GPIO4_B5, 268 MIPICAM0_RST_L_GPIO3_B6, 269 MIPICAM1_RST_L_GPIO3_B5, 270 I2C5_SCL_M0, 271 GND22, 272 I2C5_SDA_M0, 273 CLK32K_OUT0_WIFI, 274 GSENSOR_INT_L_GPIO3_C1, 275 RK809_32KOUT_WIFI, 276 SPDIF_TX_M1, 277 GND23, 278 GND52, 279 SDMMC2_D0_M0/CIF_D0, 280 SDMMC2_CLK_M0/CIF_D5, 281 SDMMC2_D1_M0/CIF_D1, 282 SDMMC2_D2_M0/CIF_D2, 283 SDMMC2_CMD_M0/CIF_D4, 284 SDMMC2_D3_M0/CIF_D3, 285 WIFI_REG_ON_H_GPIO3_D5/CIF_D7, 286 GND53, 287 GND24, 288 GMAC1_RXD2_M1/CIF_D11, 289 GMAC1_TXCLK_M1/CIF_D10, 290 WIFI_WAKE_HOST_H_GPIO3_D4/CIF_D6, 291 GMAC1_RXCLK_M1/CIF_D13, 292 CIF_D14/EBC_SDDO14/GMAC1_TXD0_M1/UART9_TX_M2/I2S2_LRCK_TX_M1/GPIO4_A4_d, 293 GMAC1_RXD3_M1/CIF_D12, 294 GMAC1_TXD1_M1/CIF_D15, 295 GMAC1_TXD3_M1/CIF_D9, 296 GMAC1_TXEN_M1, 297 GMAC1_TXD2_M1/CIF_D8, 298 GMAC1_RXD0_M1/CAM_CLKOUT0, 299 GMAC1_RXD1_M1/CAM_CLKOUT1, 300 GMAC1_RXDV_CRS_M1, 301 GND25, 302 GMAC1_MCLKINOUT_M1/CIF_CLKIN, 303 CIF_CLKOUT, 304 GND54, 305 GND26, 306 USB2_HOST3_DP, 307 GMAC1_MDIO_M1/CIF_VSYNC, 308 USB2_HOST3_DM, 309 GMAC1_MDC_M1/CIF_HREF, 310 USB2_HOST2_DP, 311 GND27, 312 USB2_HOST2_DM, 313 I2C4_SCL_M0, 314 I2C4_SDA_M0, 315 GND_1, 316 GND_2

## CRYSTAL_4P
designator Y?
CLASS: IC
pins: 1, 2 GND1 (power), 3, 4 GND2 (power)

## DC-044A-20A
designator J?
footprint dc_in_th_3p_10r1x11r6
pins: 1, 2, 3, 4, 5, 6

## DIODE
designator D?
pins: 1 A, 2 K

## DIODE BI-DIR TRIG
designator D?
footprint D0603/SMD
pins: 1, 2

## DIODE_SCHTKY
designator D?
CLASS: IC
pins: 1, 2

## FE1.1s-BQFN24B
designator U?
pins: 1 OVCJ, 2 TESTJ, 3 XOUT, 4 XIN, 5 DM4, 6 DP4, 7 DM3, 8 DP3, 9 DM2, 10 DP2, 11 DM1, 12 DP1, 13 REXT, 14 DMU, 15 DPU, 16 XRSTJ, 17 VBUSM, 18 BUSJ, 19 VDD5, 20 VDD33F, 21 DRV, 22 LED1, 23 LED2, 24 PWRJ, 25 VSS

## FPC-05F-30PH20
designator J?
footprint FPC-30P-0P5
pins: 1, 2, 3, 4, 5, 6, 7, 8, 9, 10, 11, 12, 13, 14, 15, 16, 17, 18, 19, 20, 21, 22, 23, 24, 25, 26, 27, 28, 29, 30, 31, 32

## FPC-24P
designator J?
pins: 1, 2, 3, 4, 5, 6, 7, 8, 9, 10, 11, 12, 13, 14, 15, 16, 17, 18, 19, 20, 21, 22, 23, 24, 25 SH1, 26 SH2

## FPC-30P
designator J?
footprint FPC-30P-0P5
pins: 1, 2, 3, 4, 5, 6, 7, 8, 9, 10, 11, 12, 13, 14, 15, 16, 17, 18, 19, 20, 21, 22, 23, 24, 25, 26, 27, 28, 29, 30, 31 SH1, 32 SH2

## FPC_24P_0P5
designator J?
pins: 1, 2, 3, 4, 5, 6, 7, 8, 9, 10, 11, 12, 13, 14, 15, 16, 17, 18, 19, 20, 21, 22, 23, 24, 25, 26

## FUSE
designator F?
pins: 1, 2

## HDMI-001C
designator U?
CLASS: IO; OriginalSymbolOrigin: (-200,650); Vendor: Comtek; VPN: 1166-2C105-211
footprint HDMI-SMD
pins: 1, 2, 3, 4, 5, 6, 7, 8, 9, 10, 11, 12, 13, 14, 15, 16, 17, 18, 19, G1 20, G2 21, G3 22, G4 23

## HY911130A
designator J?
pins: 1 CT, 2 TD1+, 3 TD1-, 4 RD1+, 5 TD2+, 6 TD2-, 7 RD1-, 8 RD2+, 9 RD2-, 10 CHS, 11 GRLA, 12 GRLC, 13 YELC, 14 YELA, 15 SH, 16 SH1

## IND
designator L?
CLASS: DISCRETE
pins: 1, 2

## IRM-V838M3-C/TR1
designator U?
pins: 1 GND1, 2 VCC, 3 OUT, 4 GND2

## LED
designator LED?
pins: 1 ANODE, 2 CATHODE

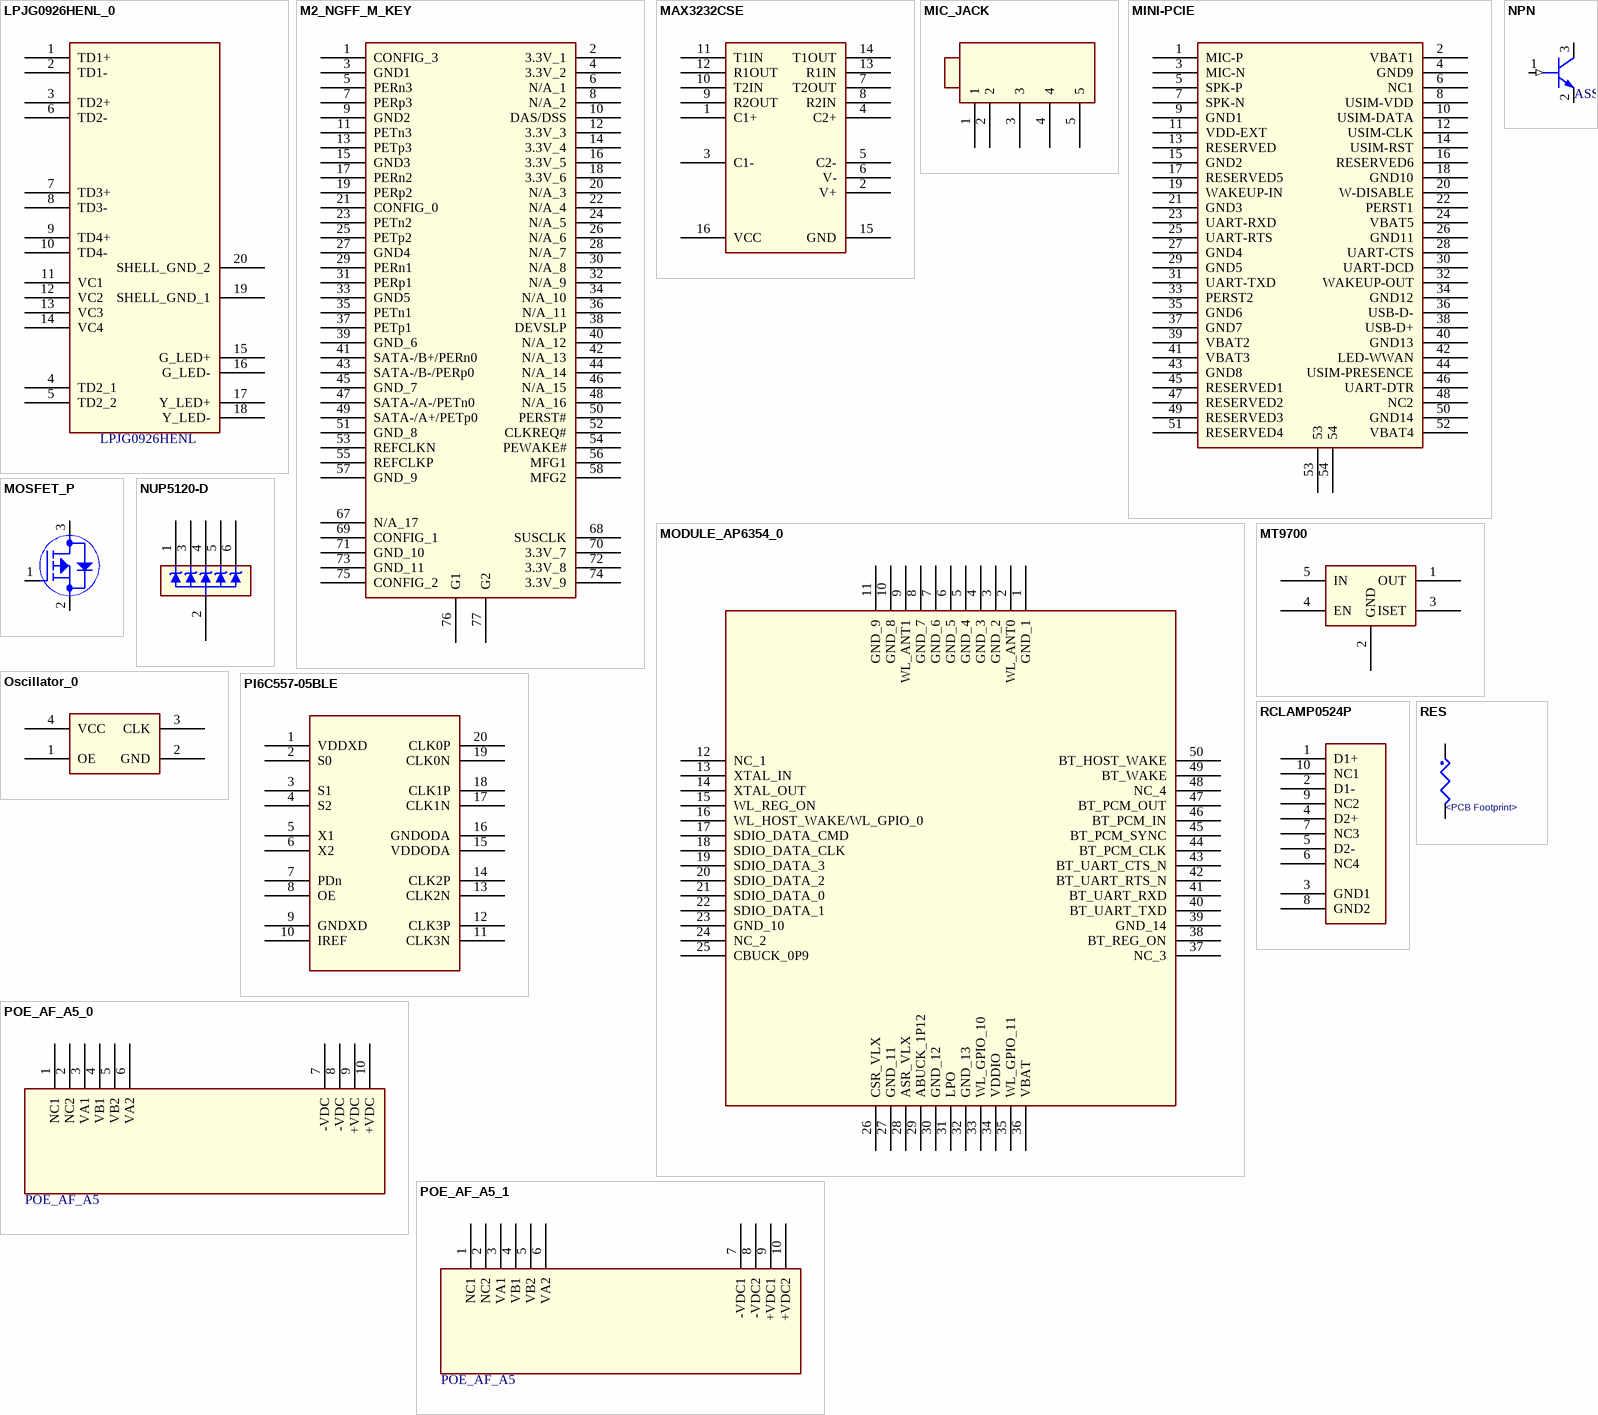
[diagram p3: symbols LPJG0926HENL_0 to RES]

## LPJG0926HENL_0
designator U?, comment LPJG0926HENL
pins: 1 TD1+, 2 TD1-, 3 TD2+, 4 TD2_1, 5 TD2_2, 6 TD2-, 7 TD3+, 8 TD3-, 9 TD4+, 10 TD4-, 11 VC1, 12 VC2, 13 VC3, 14 VC4, 15 G_LED+, 16 G_LED-, 17 Y_LED+, 18 Y_LED-, 19 SHELL_GND_1, 20 SHELL_GND_2

## M2_NGFF_M_KEY
designator J?
footprint M2_NGFF_M_KEY
pins: 1 CONFIG_3, 2 3.3V_1, 3 GND1, 4 3.3V_2, 5 PERn3, 6 N/A_1, 7 PERp3, 8 N/A_2, 9 GND2, 10 DAS/DSS, 11 PETn3, 12 3.3V_3, 13 PETp3, 14 3.3V_4, 15 GND3, 16 3.3V_5, 17 PERn2, 18 3.3V_6, 19 PERp2, 20 N/A_3, 21 CONFIG_0, 22 N/A_4, 23 PETn2, 24 N/A_5, 25 PETp2, 26 N/A_6, 27 GND4, 28 N/A_7, 29 PERn1, 30 N/A_8, 31 PERp1, 32 N/A_9, 33 GND5, 34 N/A_10, 35 PETn1, 36 N/A_11, 37 PETp1, 38 DEVSLP, 39 GND_6, 40 N/A_12, 41 SATA-/B+/PERn0, 42 N/A_13, 43 SATA-/B-/PERp0, 44 N/A_14, 45 GND_7, 46 N/A_15, 47 SATA-/A-/PETn0, 48 N/A_16, 49 SATA-/A+/PETp0, 50 PERST#, 51 GND_8, 52 CLKREQ#, 53 REFCLKN, 54 PEWAKE#, 55 REFCLKP, 56 MFG1, 57 GND_9, 58 MFG2, 67 N/A_17, 68 SUSCLK, 69 CONFIG_1, 70 3.3V_7, 71 GND_10, 72 3.3V_8, 73 GND_11, 74 3.3V_9, 75 CONFIG_2, 76 G1, 77 G2

## MAX3232CSE
designator U?
footprint 16
pins: 1 C1+, 2 V+, 3 C1-, 4 C2+, 5 C2-, 6 V-, 7 T2OUT, 8 R2IN, 9 R2OUT, 10 T2IN, 11 T1IN, 12 R1OUT, 13 R1IN, 14 T1OUT, 15 GND (power), 16 VCC (power)

## MIC_JACK
designator J?
footprint EAR_JACK
pins: 1, 2, 3, 4, 5

## MINI-PCIE
designator J?
footprint pcie_52p
pins: 1 MIC-P, 2 VBAT1, 3 MIC-N, 4 GND9, 5 SPK-P, 6 NC1, 7 SPK-N, 8 USIM-VDD, 9 GND1, 10 USIM-DATA, 11 VDD-EXT, 12 USIM-CLK, 13 RESERVED, 14 USIM-RST, 15 GND2, 16 RESERVED6, 17 RESERVED5, 18 GND10, 19 WAKEUP-IN, 20 W-DISABLE, 21 GND3, 22 PERST1, 23 UART-RXD, 24 VBAT5, 25 UART-RTS, 26 GND11, 27 GND4, 28 UART-CTS, 29 GND5, 30 UART-DCD, 31 UART-TXD, 32 WAKEUP-OUT, 33 PERST2, 34 GND12, 35 GND6, 36 USB-D-, 37 GND7, 38 USB-D+, 39 VBAT2, 40 GND13, 41 VBAT3, 42 LED-WWAN, 43 GND8, 44 USIM-PRESENCE, 45 RESERVED1, 46 UART-DTR, 47 RESERVED2, 48 NC2, 49 RESERVED3, 50 GND14, 51 RESERVED4, 52 VBAT4, 53, 54

## MODULE_AP6354_0
designator U?
pins: 1 GND_1, 2 WL_ANT0, 3 GND_2, 4 GND_3, 5 GND_4, 6 GND_5, 7 GND_6, 8 GND_7, 9 WL_ANT1, 10 GND_8, 11 GND_9, 12 NC_1, 13 XTAL_IN, 14 XTAL_OUT, 15 WL_REG_ON, 16 WL_HOST_WAKE/WL_GPIO_0, 17 SDIO_DATA_CMD, 18 SDIO_DATA_CLK, 19 SDIO_DATA_3, 20 SDIO_DATA_2, 21 SDIO_DATA_0, 22 SDIO_DATA_1, 23 GND_10, 24 NC_2, 25 CBUCK_0P9, 26 CSR_VLX, 27 GND_11, 28 ASR_VLX, 29 ABUCK_1P12, 30 GND_12, 31 LPO, 32 GND_13, 33 WL_GPIO_10, 34 VDDIO, 35 WL_GPIO_11, 36 VBAT, 37 NC_3, 38 BT_REG_ON, 39 GND_14, 40 BT_UART_TXD, 41 BT_UART_RXD, 42 BT_UART_RTS_N, 43 BT_UART_CTS_N, 44 BT_PCM_CLK, 45 BT_PCM_SYNC, 46 BT_PCM_IN, 47 BT_PCM_OUT, 48 NC_4, 49 BT_WAKE, 50 BT_HOST_WAKE

## MOSFET_P
designator Q?
CLASS: IC
pins: 1 GATE, 2 SOURCE, 3 DRAIN

## MT9700
designator U?
pins: 1 OUT, 2 GND, 3 ISET, 4 EN, 5 IN

## NPN
designator Q?
CLASS: IC
pins: 1 BASE (in), 2 EMITTER, 3 COLLECTOR

## NUP5120-D
designator U?
pins: 1, 2, 3, 4, 5, 6

## Oscillator_0
designator Y?
footprint 3225
pins: 1 OE, 2 GND, 3 CLK, 4 VCC

## PI6C557-05BLE
designator U?
footprint TSSOP20
pins: 1 VDDXD, 2 S0, 3 S1, 4 S2, 5 X1, 6 X2, 7 PDn, 8 OE, 9 GNDXD, 10 IREF, 11 CLK3N, 12 CLK3P, 13 CLK2N, 14 CLK2P, 15 VDDODA, 16 GNDODA, 17 CLK1N, 18 CLK1P, 19 CLK0N, 20 CLK0P

## POE_AF_A5_0
designator U?, comment POE_AF_A5
pins: 1 NC1, 2 NC2, 3 VA1, 4 VB1, 5 VB2, 6 VA2, 7 -VDC, 8 -VDC, 9 +VDC, 10 +VDC

## POE_AF_A5_1
designator U?, comment POE_AF_A5
pins: 1 NC1, 2 NC2, 3 VA1, 4 VB1, 5 VB2, 6 VA2, 7 -VDC1, 8 -VDC2, 9 +VDC1, 10 +VDC2

## RCLAMP0524P
designator U?
pins: 1 D1+, 2 D1-, 3 GND1, 4 D2+, 5 D2-, 6 NC4, 7 NC3, 8 GND2, 9 NC2, 10 NC1

## RES
designator R?  PCB Footprint: <PCB Footprint>
CLASS: DISCRETE
pins: 1, 2

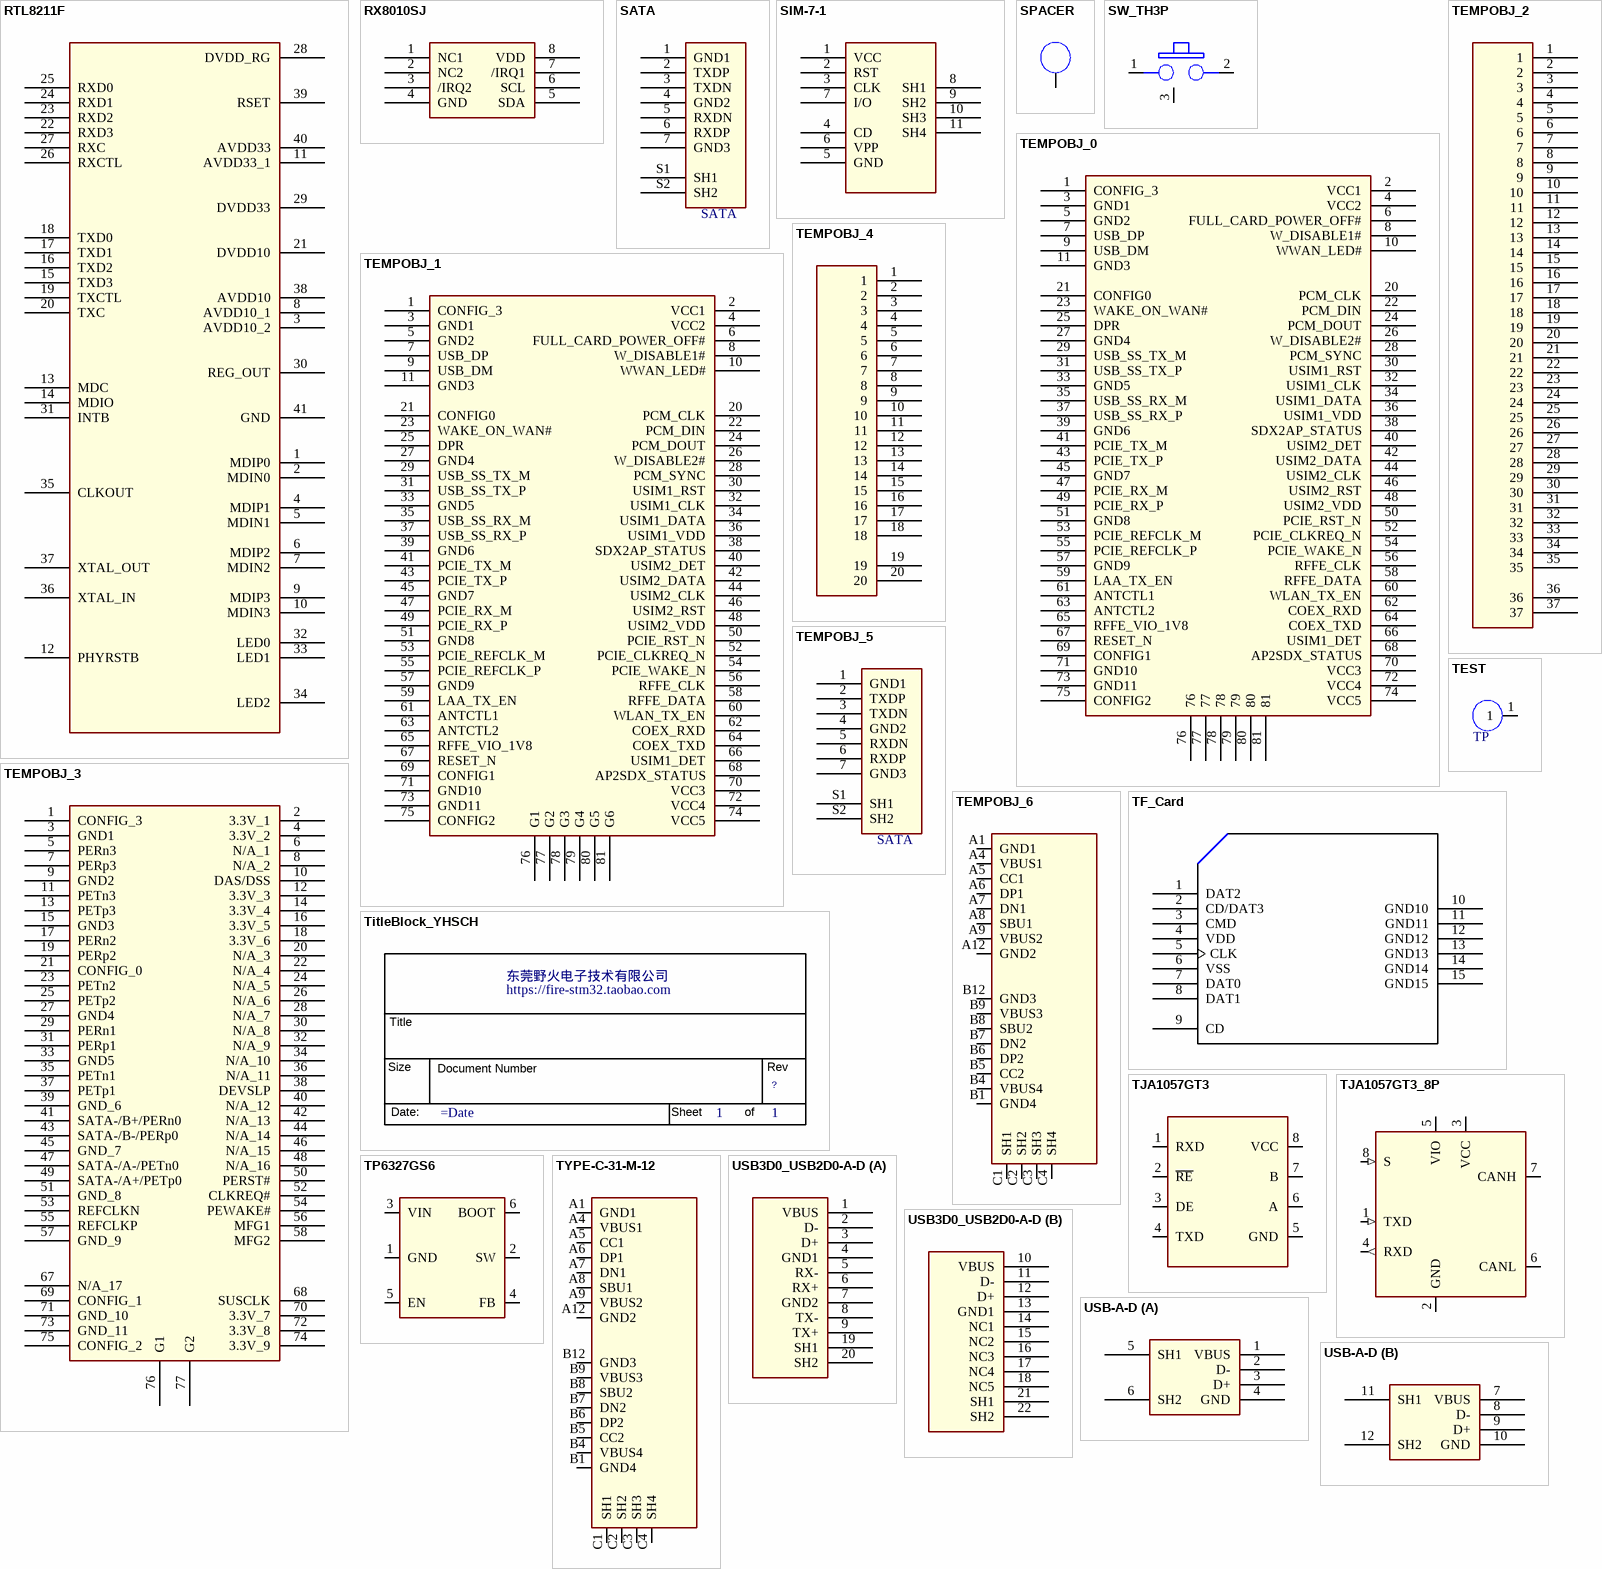
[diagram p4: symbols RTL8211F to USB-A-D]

## RTL8211F
designator U?
pins: 1 MDIP0, 2 MDIN0, 3 AVDD10_2, 4 MDIP1, 5 MDIN1, 6 MDIP2, 7 MDIN2, 8 AVDD10_1, 9 MDIP3, 10 MDIN3, 11 AVDD33_1, 12 PHYRSTB, 13 MDC, 14 MDIO, 15 TXD3, 16 TXD2, 17 TXD1, 18 TXD0, 19 TXCTL, 20 TXC, 21 DVDD10, 22 RXD3, 23 RXD2, 24 RXD1, 25 RXD0, 26 RXCTL, 27 RXC, 28 DVDD_RG, 29 DVDD33, 30 REG_OUT, 31 INTB, 32 LED0, 33 LED1, 34 LED2, 35 CLKOUT, 36 XTAL_IN, 37 XTAL_OUT, 38 AVDD10, 39 RSET, 40 AVDD33, 41 GND

## RX8010SJ
designator U?
pins: 1 NC1, 2 NC2, 3 /IRQ2, 4 GND, 5 SDA, 6 SCL, 7 /IRQ1, 8 VDD

## SATA
designator U?
footprint ssata_v
pins: 1 GND1, 2 TXDP, 3 TXDN, 4 GND2, 5 RXDN, 6 RXDP, 7 GND3, S1 SH1 (power), S2 SH2 (power)

## SIM-7-1
designator U?
pins: 1 VCC, 2 RST, 3 CLK, 4 CD, 5 GND, 6 VPP, 7 I/O, 8 SH1, 9 SH2, 10 SH3, 11 SH4

## SPACER
designator SS?
CLASS: IC
pins: 1 NC_1

## SW_TH3P
designator SW?  (value not drawn)
CLASS: IC
pins: 1 A1, 2 B1, 3 GND1

## TEMPOBJ_0
designator U?
footprint M2_NGFF_B_KEY
pins: 1 CONFIG_3, 2 VCC1, 3 GND1, 4 VCC2, 5 GND2, 6 FULL_CARD_POWER_OFF#, 7 USB_DP, 8 W_DISABLE1#, 9 USB_DM, 10 WWAN_LED#, 11 GND3, 20 PCM_CLK, 21 CONFIG0, 22 PCM_DIN, 23 WAKE_ON_WAN#, 24 PCM_DOUT, 25 DPR, 26 W_DISABLE2#, 27 GND4, 28 PCM_SYNC, 29 USB_SS_TX_M, 30 USIM1_RST, 31 USB_SS_TX_P, 32 USIM1_CLK, 33 GND5, 34 USIM1_DATA, 35 USB_SS_RX_M, 36 USIM1_VDD, 37 USB_SS_RX_P, 38 SDX2AP_STATUS, 39 GND6, 40 USIM2_DET, 41 PCIE_TX_M, 42 USIM2_DATA, 43 PCIE_TX_P, 44 USIM2_CLK, 45 GND7, 46 USIM2_RST, 47 PCIE_RX_M, 48 USIM2_VDD, 49 PCIE_RX_P, 50 PCIE_RST_N, 51 GND8, 52 PCIE_CLKREQ_N, 53 PCIE_REFCLK_M, 54 PCIE_WAKE_N, 55 PCIE_REFCLK_P, 56 RFFE_CLK, 57 GND9, 58 RFFE_DATA, 59 LAA_TX_EN, 60 WLAN_TX_EN, 61 ANTCTL1, 62 COEX_RXD, 63 ANTCTL2, 64 COEX_TXD, 65 RFFE_VIO_1V8, 66 USIM1_DET, 67 RESET_N, 68 AP2SDX_STATUS, 69 CONFIG1, 70 VCC3, 71 GND10, 72 VCC4, 73 GND11, 74 VCC5, 75 CONFIG2, 76, 77, 78, 79, 80, 81

## TEMPOBJ_1
designator U?
footprint M2_NGFF_B_KEY
pins: 1 CONFIG_3, 2 VCC1, 3 GND1, 4 VCC2, 5 GND2, 6 FULL_CARD_POWER_OFF#, 7 USB_DP, 8 W_DISABLE1#, 9 USB_DM, 10 WWAN_LED#, 11 GND3, 20 PCM_CLK, 21 CONFIG0, 22 PCM_DIN, 23 WAKE_ON_WAN#, 24 PCM_DOUT, 25 DPR, 26 W_DISABLE2#, 27 GND4, 28 PCM_SYNC, 29 USB_SS_TX_M, 30 USIM1_RST, 31 USB_SS_TX_P, 32 USIM1_CLK, 33 GND5, 34 USIM1_DATA, 35 USB_SS_RX_M, 36 USIM1_VDD, 37 USB_SS_RX_P, 38 SDX2AP_STATUS, 39 GND6, 40 USIM2_DET, 41 PCIE_TX_M, 42 USIM2_DATA, 43 PCIE_TX_P, 44 USIM2_CLK, 45 GND7, 46 USIM2_RST, 47 PCIE_RX_M, 48 USIM2_VDD, 49 PCIE_RX_P, 50 PCIE_RST_N, 51 GND8, 52 PCIE_CLKREQ_N, 53 PCIE_REFCLK_M, 54 PCIE_WAKE_N, 55 PCIE_REFCLK_P, 56 RFFE_CLK, 57 GND9, 58 RFFE_DATA, 59 LAA_TX_EN, 60 WLAN_TX_EN, 61 ANTCTL1, 62 COEX_RXD, 63 ANTCTL2, 64 COEX_TXD, 65 RFFE_VIO_1V8, 66 USIM1_DET, 67 RESET_N, 68 AP2SDX_STATUS, 69 CONFIG1, 70 VCC3, 71 GND10, 72 VCC4, 73 GND11, 74 VCC5, 75 CONFIG2, 76 G1, 77 G2, 78 G3, 79 G4, 80 G5, 81 G6

## TEMPOBJ_2
designator J?
footprint FPC-30P-0P5
pins: 1, 2, 3, 4, 5, 6, 7, 8, 9, 10, 11, 12, 13, 14, 15, 16, 17, 18, 19, 20, 21, 22, 23, 24, 25, 26, 27, 28, 29, 30, 31, 32, 33, 34, 35, 36, 37

## TEMPOBJ_3
designator J?
footprint M2_NGFF_M_KEY
pins: 1 CONFIG_3, 2 3.3V_1, 3 GND1, 4 3.3V_2, 5 PERn3, 6 N/A_1, 7 PERp3, 8 N/A_2, 9 GND2, 10 DAS/DSS, 11 PETn3, 12 3.3V_3, 13 PETp3, 14 3.3V_4, 15 GND3, 16 3.3V_5, 17 PERn2, 18 3.3V_6, 19 PERp2, 20 N/A_3, 21 CONFIG_0, 22 N/A_4, 23 PETn2, 24 N/A_5, 25 PETp2, 26 N/A_6, 27 GND4, 28 N/A_7, 29 PERn1, 30 N/A_8, 31 PERp1, 32 N/A_9, 33 GND5, 34 N/A_10, 35 PETn1, 36 N/A_11, 37 PETp1, 38 DEVSLP, 39 GND_6, 40 N/A_12, 41 SATA-/B+/PERn0, 42 N/A_13, 43 SATA-/B-/PERp0, 44 N/A_14, 45 GND_7, 46 N/A_15, 47 SATA-/A-/PETn0, 48 N/A_16, 49 SATA-/A+/PETp0, 50 PERST#, 51 GND_8, 52 CLKREQ#, 53 REFCLKN, 54 PEWAKE#, 55 REFCLKP, 56 MFG1, 57 GND_9, 58 MFG2, 67 N/A_17, 68 SUSCLK, 69 CONFIG_1, 70 3.3V_7, 71 GND_10, 72 3.3V_8, 73 GND_11, 74 3.3V_9, 75 CONFIG_2, 76 G1, 77 G2

## TEMPOBJ_4
designator J?
footprint FPC-18P-0P5
pins: 1, 2, 3, 4, 5, 6, 7, 8, 9, 10, 11, 12, 13, 14, 15, 16, 17, 18, 19, 20

## TEMPOBJ_5
designator U?, comment SATA
footprint ssata_v
pins: 1 GND1, 2 TXDP, 3 TXDN, 4 GND2, 5 RXDN, 6 RXDP, 7 GND3, S1 SH1 (power), S2 SH2 (power)

## TEMPOBJ_6
designator J?
footprint TYPE-C-31-M-12
pins: A1 GND1, A4 VBUS1, A5 CC1, A6 DP1, A7 DN1, A8 SBU1, A9 VBUS2, A12 GND2, B1 GND4, B4 VBUS4, B5 CC2, B6 DP2, B7 DN2, B8 SBU2, B9 VBUS3, B12 GND3, C1 SH1, C2 SH2, C3 SH3, C4 SH4

## TEST
designator J?, comment TP
pins: 1

## TF_Card
designator J?
CLASS: IO
pins: 1 DAT2, 2 CD/DAT3, 3 CMD, 4 VDD (power), 5 CLK, 6 VSS (power), 7 DAT0, 8 DAT1, 9 CD, 10 GND10, 11 GND11, 12 GND12, 13 GND13, 14 GND14, 15 GND15

## TitleBlock_YHSCH
designator *  OrgName: 东莞野火电子技术有限公司  Page Number: 1  (hidden comment: *)  (graphical)

## TJA1057GT3
designator U?
CLASS: IC
pins: 1 RXD, 2 ~{RE}, 3 DE, 4 TXD, 5 GND, 6 A, 7 B, 8 VCC

## TJA1057GT3_8P
designator U?
CLASS: IC
pins: 1 TXD (in), 2 GND (power), 3 VCC (power), 4 RXD (out), 5 VIO (power), 6 CANL (io), 7 CANH (io), 8 S (in)

## TP6327GS6
designator U?
pins: 1 GND, 2 SW, 3 VIN, 4 FB, 5 EN, 6 BOOT

## TYPE-C-31-M-12
designator J?
footprint TYPE-C-31-M-12
pins: A1 GND1, A4 VBUS1, A5 CC1, A6 DP1, A7 DN1, A8 SBU1, A9 VBUS2, A12 GND2, B1 GND4, B4 VBUS4, B5 CC2, B6 DP2, B7 DN2, B8 SBU2, B9 VBUS3, B12 GND3, C1 SH1, C2 SH2, C3 SH3, C4 SH4

## USB3D0_USB2D0-A-D
designator J?
footprint USB3D0-AF-18P
part A pins: 1 VBUS, 2 D-, 3 D+, 4 GND1, 5 RX-, 6 RX+, 7 GND2, 8 TX-, 9 TX+, 19 SH1, 20 SH2
part B pins: 10 VBUS, 11 D-, 12 D+, 13 GND1, 14 NC1, 15 NC2, 16 NC3, 17 NC4, 18 NC5, 21 SH1, 22 SH2

## USB-A-D
designator J?
footprint USB-A-D
part A pins: 1 VBUS, 2 D-, 3 D+, 4 GND, 5 SH1, 6 SH2
part B pins: 7 VBUS, 8 D-, 9 D+, 10 GND, 11 SH1, 12 SH2

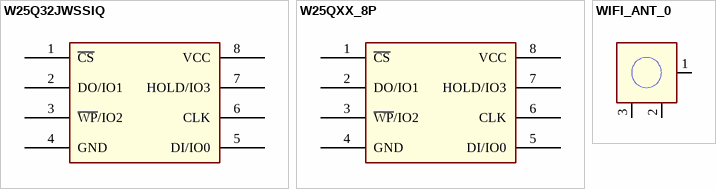
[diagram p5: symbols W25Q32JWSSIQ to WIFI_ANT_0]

## W25Q32JWSSIQ
designator U?
pins: 1 ~{CS}, 2 DO/IO1, 3 ~{WP}/IO2, 4 GND, 5 DI/IO0, 6 CLK, 7 HOLD/IO3, 8 VCC

## W25QXX_8P
designator U?
pins: 1 ~{CS}, 2 DO/IO1, 3 ~{WP}/IO2, 4 GND, 5 DI/IO0, 6 CLK, 7 HOLD/IO3, 8 VCC

## WIFI_ANT_0
designator CN?
footprint UFL-3
pins: 1, 2, 3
